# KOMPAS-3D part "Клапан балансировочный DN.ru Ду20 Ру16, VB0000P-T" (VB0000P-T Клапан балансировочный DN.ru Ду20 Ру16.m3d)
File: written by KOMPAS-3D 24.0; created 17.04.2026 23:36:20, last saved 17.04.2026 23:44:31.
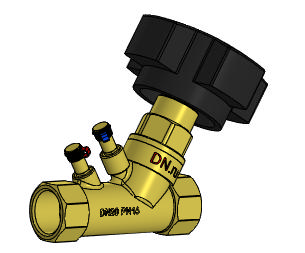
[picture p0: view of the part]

Document properties: Автор: tyuri; Полное имя файла: E:\Работа\Зайцев\АУТСОРС\Диман\Балансировка\VB0000P-T Клапан балансировочный DN.ru Ду15-50 Ру16\DN20\VB0000P-T Клапан балансировочный DN.ru Ду20 Ру16.m3d

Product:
- Body: Тело 2  | qty 1
    Масса: 0.925551
- Part/product: Клапан балансировочный DN.ru Ду20 Ру16  | designation VB0000P-T
    Масса: 0.415
    Раздел спецификации: Прочие изделия
    Примечание: D080-01092

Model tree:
1. Операция без истории:1

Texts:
  Точка начала. Х
  Точка начала. Y
  Точка начала. Z
  VB0000P-T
